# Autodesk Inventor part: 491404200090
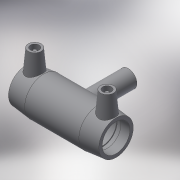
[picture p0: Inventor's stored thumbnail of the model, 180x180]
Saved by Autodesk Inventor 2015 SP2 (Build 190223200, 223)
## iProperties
Created: 2017-06
Part Number: 491404200090
Material: Generic
Description: PLASSON REDUCING TEE 200x90x200
Document SubType Name: Modeling
Designer: KIM
Mass: 57.3761 g
Surface Area: 241.06 cm^2
Volume: 57.3761 cm^3
Density: 1 g/cm^3
Appearance: Default
Author: KIM
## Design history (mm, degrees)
derived "491404.ipt"
feature "Solid1::491404.ipt"
tag "TaggingFeature1"
body "Solid1"
other parameters: "d0" = 451, "d2" = 261, "d3" = 114, "d4" = 90.2, "d5" = 234.9, "d8" = 168 deg, "d10" = 45.6, "d11" = 15.2, "d13" = 451, "d14" = 17.6296, "d19" = 3.52592, "d20" = 168 deg, "d22" = 242.73, "d23" = 261, "d25" = 135 deg, "d26" = 315.7, "d29" = 125, "d30" = 15, "d31" = 180.4, "d34" = 5 deg, "d35" = 15, "d39" = 5 deg, "d41" = 4, "d42" = 14, "d43" = 0, "d45" = 4, "d46" = 6, "d47" = 0, "d48" = -205, "d51" = 0, "d52" = 72, "d54" = 0, "d55" = 234.9, "d56" = 261, "d57" = 157.85, "d58" = 135 deg, "d59" = 114, "d60" = 114, "d61" = 135 deg, "d62" = 205, "d72" = 205.205, "d73" = 102.6025, "d74" = -205, "d75" = 94.5, "d77" = 0, "d78" = 72, "d80" = 0, "d82" = 74.5, "d83" = 0, "d84" = 3, "d85" = 0, "d86" = 38, "d87" = 237.8754, "d88" = 15.2, "d89" = 3, "d90" = 0, "L_" = 451, "L_1" = 114, "D_" = 261, "A_" = 125, "d_2" = 12, "H_" = 205
